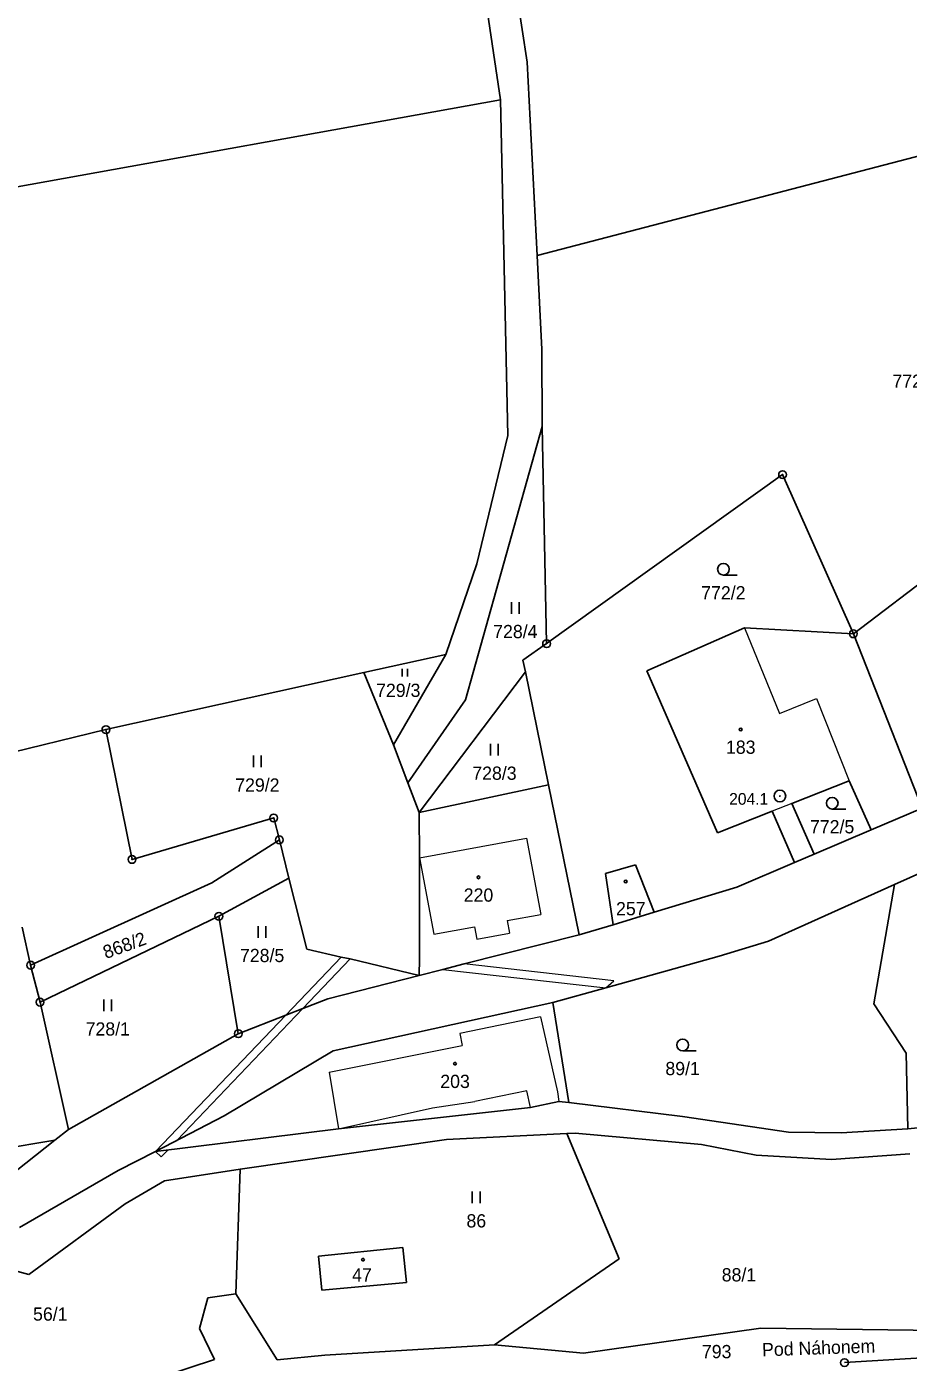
# Model space of a CAD drawing. Extents: x -739410 to -735662, y -942282 to -940043.
# Drawn here: x -737914.5 to -737801.3, y -941365.5 to -941193.9 of the extents above; entities that cross this region are included whole.
import ezdxf
from ezdxf.enums import TextEntityAlignment as Align

# ---------------------------------------------------------------- set-up
doc = ezdxf.new("R2010")
doc.units = 0
doc.header["$LTSCALE"] = 0.68
for name, color, linetype, lineweight in [('1', 7, 'Continuous', 25), ('13', 7, 'Continuous', 13), ('3', 7, 'Continuous', 25), ('4', 7, 'Continuous', 13), ('5', 7, 'Continuous', 25), ('7', 7, 'Continuous', 13), ('8', 7, 'Continuous', 25)]:
    doc.layers.add(name, color=color, linetype=linetype, lineweight=lineweight)
doc.layers.add('2', color=7, linetype='Continuous')

msp = doc.modelspace()

# ---------------------------------------------------------------- linework, layer by layer
at = {"layer": '1'}
for p, q in [((-737850.23, -941198.5), (-737856.12, -941159.67)), ((-737853.64, -941203.35), (-737859.66, -941162.75)), ((-737848.95, -941223.33), (-737850.23, -941198.5)), ((-737947.15, -941220.19), (-737853.64, -941203.35)), ((-737852.7, -941246.45), (-737853.64, -941203.35)), ((-737848.95, -941223.33), (-737772.88, -941203.51)), ((-737848.32, -941235.42), (-737848.95, -941223.33)), ((-737848.28, -941245.3), (-737848.32, -941235.42)), ((-737808.35, -941271.91), (-737758.32, -941233.86)), ((-737858.15, -941280.41), (-737848.28, -941245.3)), ((-737847.73, -941273.18), (-737848.28, -941245.3)), ((-737856.69, -941262.92), (-737852.7, -941246.45)), ((-737847.73, -941273.18), (-737817.44, -941251.47)), ((-737817.44, -941251.47), (-737808.35, -941271.91)), ((-737860.66, -941274.56), (-737856.69, -941262.92)), ((-737834.86, -941276.67), (-737822.33, -941271.13)), ((-737808.35, -941271.91), (-737822.33, -941271.13)), ((-737847.73, -941273.18), (-737850.77, -941275.32)), ((-737808.35, -941271.91), (-737799.51, -941294.3)), ((-737871.19, -941276.9), (-737860.66, -941274.56)), ((-737860.66, -941274.56), (-737867.4, -941286.18)), ((-737850.45, -941276.78), (-737850.77, -941275.32)), ((-737904.29, -941284.22), (-737871.19, -941276.9)), ((-737867.4, -941286.18), (-737871.19, -941276.9)), ((-737864.1, -941294.88), (-737850.45, -941276.78)), ((-737847.47, -941291.32), (-737850.45, -941276.78)), ((-737825.8, -941297.49), (-737834.86, -941276.67)), ((-737865.55, -941291.05), (-737858.15, -941280.41)), ((-737941.53, -941293.31), (-737904.29, -941284.22)), ((-737904.29, -941284.22), (-737900.94, -941300.89)), ((-737865.55, -941291.05), (-737867.4, -941286.18)), ((-737865.55, -941291.05), (-737864.1, -941294.88)), ((-737864.1, -941294.88), (-737847.47, -941291.32)), ((-737843.54, -941310.59), (-737847.47, -941291.32)), ((-737808.89, -941290.79), (-737816.24, -941293.7)), ((-737806.06, -941297.1), (-737808.89, -941290.79)), ((-737813.4, -941300.23), (-737816.24, -941293.7)), ((-737864.04, -941300.68), (-737864.1, -941294.88)), ((-737818.76, -941294.7), (-737825.8, -941297.49)), ((-737815.89, -941301.29), (-737818.76, -941294.7)), ((-737806.06, -941297.1), (-737799.51, -941294.3)), ((-737882.75, -941295.57), (-737900.94, -941300.89)), ((-737882.03, -941298.38), (-737882.75, -941295.57)), ((-737813.4, -941300.23), (-737806.06, -941297.1)), ((-737786.6, -941296.7), (-737803.08, -941304.12)), ((-737890.68, -941303.91), (-737882.03, -941298.38)), ((-737882.03, -941298.38), (-737880.8, -941303.31)), ((-737815.89, -941301.29), (-737813.4, -941300.23)), ((-737864.04, -941300.68), (-737864.05, -941313.61)), ((-737840.15, -941302.68), (-737836.31, -941301.57)), ((-737836.31, -941301.57), (-737833.91, -941307.66)), ((-737823.32, -941304.45), (-737815.89, -941301.29)), ((-737913.95, -941314.48), (-737890.68, -941303.91)), ((-737889.79, -941308.19), (-737880.8, -941303.31)), ((-737880.8, -941303.31), (-737878.52, -941312.43)), ((-737840.15, -941302.68), (-737839.2, -941309.27)), ((-737833.91, -941307.66), (-737823.32, -941304.45)), ((-737803.08, -941304.12), (-737819.24, -941311.39)), ((-737803.08, -941304.12), (-737805.71, -941319.45)), ((-737912.75, -941319.22), (-737889.79, -941308.19)), ((-737889.79, -941308.19), (-737887.3, -941323.27)), ((-737839.2, -941309.27), (-737833.91, -941307.66)), ((-737913.95, -941314.48), (-737915.05, -941309.58)), ((-737843.54, -941310.59), (-737839.2, -941309.27)), ((-737819.24, -941311.39), (-737825.58, -941313.3)), ((-737864.05, -941313.61), (-737864.09, -941315.79)), ((-737913.95, -941314.48), (-737912.75, -941319.22)), ((-737875.8, -941318.79), (-737864.09, -941315.79)), ((-737909.08, -941335.57), (-737912.75, -941319.22)), ((-737846.91, -941319.28), (-737875.12, -941325.49)), ((-737844.86, -941332.09), (-737846.91, -941319.28)), ((-737805.71, -941319.45), (-737801.59, -941325.79)), ((-737887.3, -941323.27), (-737909.08, -941335.57)), ((-737875.12, -941325.49), (-737889.1, -941333.84)), ((-737801.59, -941325.79), (-737801.37, -941335.51)), ((-737849.79, -941332.77), (-737874.44, -941335.51)), ((-737846.17, -941331.98), (-737849.79, -941332.77)), ((-737844.86, -941332.09), (-737846.17, -941331.98)), ((-737844.86, -941332.09), (-737830.27, -941333.9)), ((-737889.1, -941333.84), (-737897.92, -941338.41)), ((-737830.27, -941333.9), (-737816.69, -941335.91)), ((-737787.11, -941334), (-737801.37, -941335.51)), ((-737909.08, -941335.57), (-737910.84, -941336.96)), ((-737897.92, -941338.41), (-737874.44, -941335.51)), ((-737860.58, -941336.86), (-737845.12, -941336.09)), ((-737845.12, -941336.09), (-737844.06, -941336.04)), ((-737838.41, -941352.2), (-737845.12, -941336.09)), ((-737827.83, -941337.51), (-737844.06, -941336.04)), ((-737816.69, -941335.91), (-737809.9, -941336.02)), ((-737809.9, -941336.02), (-737801.37, -941335.51)), ((-737910.84, -941336.96), (-737932.48, -941353.98)), ((-737918.04, -941338.16), (-737910.84, -941336.96)), ((-737887.04, -941340.67), (-737860.58, -941336.86)), ((-737820.83, -941338.89), (-737827.83, -941337.51)), ((-737897.92, -941338.41), (-737902.72, -941340.82)), ((-737811.17, -941339.42), (-737820.83, -941338.89)), ((-737801.1, -941338.69), (-737811.17, -941339.42)), ((-737915.4, -941348.15), (-737902.72, -941340.82)), ((-737896.78, -941342.18), (-737887.04, -941340.67)), ((-737887.04, -941340.67), (-737887.63, -941356.69)), ((-737901.82, -941345.13), (-737896.78, -941342.18)), ((-737914.19, -941354.19), (-737901.82, -941345.13)), ((-737877.01, -941351.86), (-737866.19, -941350.74)), ((-737876.56, -941356.2), (-737877.01, -941351.86)), ((-737866.19, -941350.74), (-737865.73, -941355.21)), ((-737916.99, -941353.43), (-737914.19, -941354.19)), ((-737838.41, -941352.2), (-737854.42, -941363.24)), ((-737865.73, -941355.21), (-737876.56, -941356.2)), ((-737891.2, -941357.2), (-737892.26, -941361.12)), ((-737887.63, -941356.69), (-737891.2, -941357.2)), ((-737887.63, -941356.69), (-737882.3, -941365.14)), ((-737892.26, -941361.12), (-737890.35, -941365.12)), ((-737843, -941364.31), (-737820.24, -941361.09)), ((-737820.24, -941361.09), (-737791.97, -941361.45)), ((-737876.2, -941364.57), (-737854.42, -941363.24)), ((-737854.42, -941363.24), (-737843, -941364.31)), ((-737890.35, -941365.12), (-737903.54, -941369.43)), ((-737882.3, -941365.14), (-737876.2, -941364.57)), ((-737809.49, -941365.51), (-737790.76, -941364.33))]:
    msp.add_line(p, q, dxfattribs=at)
for points in [[(-737864.09, -941315.79), (-737861.03, -941315.02), (-737858.3, -941314.32), (-737843.54, -941310.59)], [(-737878.52, -941312.43), (-737874.11, -941313.46), (-737872.94, -941313.67), (-737864.09, -941315.79)], [(-737825.58, -941313.3), (-737840.12, -941317.38), (-737846.91, -941319.28)], [(-737887.3, -941323.27), (-737881.21, -941320.9), (-737879.02, -941320.04), (-737875.8, -941318.79)]]:
    msp.add_lwpolyline(points, dxfattribs=at)
at = {"layer": '13'}
for points in [[(-737874.11, -941313.46), (-737881.21, -941320.9), (-737879.02, -941320.04), (-737872.94, -941313.67)], [(-737861.03, -941315.02), (-737840.12, -941317.38), (-737839.11, -941316.49), (-737858.3, -941314.32)], [(-737895.18, -941336.99), (-737879.02, -941320.04), (-737881.21, -941320.9), (-737897.92, -941338.41)], [(-737897.92, -941338.41), (-737897.19, -941339.1), (-737896.35, -941338.22)]]:
    msp.add_lwpolyline(points, close=True, dxfattribs=at)
at = {"layer": '3'}
for p, q in [((-737825.033, -941264.37), (-737823.283, -941264.37)), ((-737852.251, -941269.35), (-737852.251, -941267.85)), ((-737851.25, -941269.35), (-737851.25, -941267.85)), ((-737866.252, -941277.4), (-737866.252, -941276.395)), ((-737865.582, -941277.4), (-737865.582, -941276.395)), ((-737854.931, -941287.54), (-737854.931, -941286.04)), ((-737853.93, -941287.54), (-737853.93, -941286.04)), ((-737885.361, -941289.06), (-737885.361, -941287.56)), ((-737884.36, -941289.06), (-737884.36, -941287.56)), ((-737811.073, -941294.42), (-737809.323, -941294.42)), ((-737884.751, -941310.95), (-737884.751, -941309.45)), ((-737883.75, -941310.95), (-737883.75, -941309.45)), ((-737904.561, -941320.39), (-737904.561, -941318.89)), ((-737903.56, -941320.39), (-737903.56, -941318.89)), ((-737830.263, -941325.47), (-737828.513, -941325.47)), ((-737857.261, -941345.03), (-737857.261, -941343.53)), ((-737856.26, -941345.03), (-737856.26, -941343.53))]:
    msp.add_line(p, q, dxfattribs=at)
for centre in [(-737825.0329, -941263.6198), (-737811.0729, -941293.6698), (-737830.2629, -941324.7198)]:
    msp.add_circle(centre, 0.75, dxfattribs=at)
at = {"layer": '4'}
for p, q in [((-737822.33, -941271.13), (-737817.83, -941282.14)), ((-737817.83, -941282.14), (-737813.08, -941280.23)), ((-737813.08, -941280.23), (-737808.89, -941290.79)), ((-737816.24, -941293.7), (-737818.76, -941294.7)), ((-737864.04, -941300.68), (-737850.32, -941298.18)), ((-737850.32, -941298.18), (-737848.48, -941307.96)), ((-737864.04, -941300.68), (-737862.19, -941310.49)), ((-737852.78, -941308.75), (-737848.48, -941307.96)), ((-737852.78, -941308.75), (-737852.48, -941310.34)), ((-737862.19, -941310.49), (-737856.99, -941309.53)), ((-737856.99, -941309.53), (-737856.69, -941311.11)), ((-737856.69, -941311.11), (-737852.48, -941310.34)), ((-737848.53, -941321.12), (-737858.86, -941323.23)), ((-737848.53, -941321.12), (-737846.35, -941330.72)), ((-737858.86, -941323.23), (-737858.58, -941324.79)), ((-737875.62, -941328.21), (-737858.58, -941324.79)), ((-737875.62, -941328.21), (-737874.44, -941335.51)), ((-737850.25, -941330.62), (-737856.92, -941331.97)), ((-737849.79, -941332.77), (-737850.25, -941330.62)), ((-737846.35, -941330.72), (-737846.17, -941331.98)), ((-737874.44, -941335.51), (-737862.36, -941332.78)), ((-737862.36, -941332.78), (-737856.92, -941331.97))]:
    msp.add_line(p, q, dxfattribs=at)
at = {"layer": '5'}
for centre in [(-737822.8168, -941284.1992), (-737856.4768, -941303.1892), (-737837.5768, -941303.7292), (-737859.4868, -941327.1192), (-737871.2968, -941352.2892)]:
    msp.add_circle(centre, 0.175, dxfattribs=at)
at = {"layer": '8'}
for centre, radius in [((-737817.44, -941251.4699), 0.5), ((-737817.44, -941251.4699), 0.0303), ((-737808.35, -941271.9099), 0.5), ((-737847.73, -941273.1799), 0.5), ((-737847.73, -941273.1799), 0.0303), ((-737808.35, -941271.9099), 0.0303), ((-737904.29, -941284.2199), 0.5), ((-737904.29, -941284.2199), 0.0303), ((-737817.78, -941292.7498), 0.75), ((-737817.78, -941292.7498), 0.03), ((-737882.75, -941295.5699), 0.5), ((-737882.75, -941295.5699), 0.0303), ((-737882.03, -941298.3799), 0.5), ((-737882.03, -941298.3799), 0.0303), ((-737900.94, -941300.8899), 0.5), ((-737900.94, -941300.8899), 0.0303), ((-737889.79, -941308.1899), 0.5), ((-737889.79, -941308.1899), 0.0303), ((-737913.95, -941314.4799), 0.5), ((-737913.95, -941314.4799), 0.0303), ((-737912.75, -941319.2199), 0.5), ((-737912.75, -941319.2199), 0.0303), ((-737887.3, -941323.2699), 0.5), ((-737887.3, -941323.2699), 0.0303), ((-737809.49, -941365.5099), 0.5)]:
    msp.add_circle(centre, radius, dxfattribs=at)

# ---------------------------------------------------------------- texts
at = {"layer": '2'}
for s, p in [('772/7', (-737800.5, -941240.325)), ('772/2', (-737825.04, -941267.495)), ('728/4', (-737851.74, -941272.475)), ('729/3', (-737866.77, -941280.025)), ('183', (-737822.809, -941287.325)), ('728/3', (-737854.42, -941290.665)), ('729/2', (-737884.85, -941292.185)), ('772/5', (-737811.08, -941297.545)), ('220', (-737856.469, -941306.315)), ('257', (-737836.919, -941308.065)), ('728/5', (-737884.24, -941314.075)), ('728/1', (-737904.05, -941323.515)), ('89/1', (-737830.269, -941328.595)), ('203', (-737859.479, -941330.245)), ('86', (-737856.749, -941348.155)), ('47', (-737871.429, -941355.105)), ('88/1', (-737823.039, -941355.085)), ('56/1', (-737911.429, -941360.125)), ('793', (-737825.899, -941364.945))]:
    msp.add_text(s, height=1.7, dxfattribs=at).set_placement(p, align=Align.CENTER)
msp.add_text('868/2', height=1.7, rotation=20, dxfattribs=at).set_placement((-737901.6162, -941312.7152), align=Align.CENTER)
at = {"layer": '7'}
msp.add_text('Pod Náhonem', height=1.7, rotation=2, dxfattribs=at).set_placement((-737820.045, -941364.714))
at = {"layer": '8'}
msp.add_text('204.1', height=1.5, dxfattribs=at).set_placement((-737819.279, -941293.867), align=Align.RIGHT)

doc.saveas('drawing.dxf')
